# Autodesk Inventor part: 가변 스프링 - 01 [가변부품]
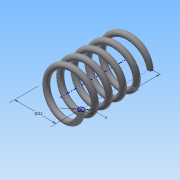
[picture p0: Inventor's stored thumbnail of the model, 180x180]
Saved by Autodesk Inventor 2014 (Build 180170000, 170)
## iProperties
Created: 2015-09
Part Number: 가변 스프링 - 01 [가변부품]
Material: 강철, 탄소
Document SubType Name: Modeling
Designer: study
Density: 1 g/cm^3
Appearance: 반연마
Author: study
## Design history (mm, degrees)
sketch "스케치1"
  geometry: L1 (0, 0)-(11, 0); L2 (11, 0)-(11, 29.193); L3 (11, 29.193)-(0, 29.193); L4 (0, 29.193)-(0, 0); C1 r 1.5 at (11, 0)
  constraints: 8 end point, 2 parallel, 1 centre point, 1 coincident, 1 horizontal, 1 perpendicular
  dimensions: "d0" = 22 diameter of L2 L4; "d1" = 29.19259 distance between parallel lines of L3 L1 (derived); "d2" = 3 diameter of C1
feature "코일1" sketch "스케치1" pitch "d3" = 10; turns "d5" = 5; dims "d4" = 29.19259 (= d1), "d6" = 0, angle "d7" = 90 deg, angle "d8" = 90 deg, "d9" = 0, "d10" = 0
node "작업 평면1"
sketch "스케치2"
  geometry: L1 (-12.5, 0)-(-9.5, 0) reference; L2 (-12.5, 0)-(-9.5, 0) reference; 1 further point
  constraints: 2 horizontal alignment
extrude "돌출1" cut sketch "스케치2" stored distance "d12" = 10; taper "d13" = 0 deg
node "작업 평면2"
sketch "스케치3"
  geometry: L1 (-9.5, 0)-(-12.5, 0) reference; 1 further point
  constraints: 1 horizontal alignment
extrude "돌출2" cut sketch "스케치3" stored distance "d15" = 10; taper "d16" = 0 deg
node "솔리드1"
node "절단 모서리 투영1"
node "절단 모서리 투영2"
node "절단 모서리 투영3"
other parameters: "d11" = 0, "d14" = 29.19259 (= d1)
